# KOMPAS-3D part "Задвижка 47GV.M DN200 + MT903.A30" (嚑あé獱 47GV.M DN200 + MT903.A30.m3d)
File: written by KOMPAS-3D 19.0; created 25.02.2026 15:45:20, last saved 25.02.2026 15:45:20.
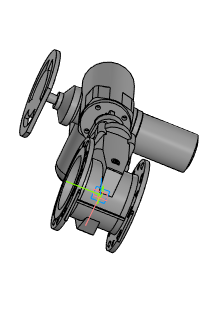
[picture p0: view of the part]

Document properties: Автор: Энергия; Полное имя файла: 47GV.M DN200\Задвижка 47GV.M DN200 с переходом под ISO фланец.a3d

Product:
- Part/product: Задвижка 47GV.M DN200 + MT903.A30
    Масса: 259.936
  - Component: Задвижка с обрезиненным клином DN200. Сборочный чертеж  | designation DR.47GVM.200.16.00.00СБ  | pos. 0  | Масса: 49.2062; Раздел спецификации: Документация; Форматы листов документа: 2xA3; source file: 47GV.M DN200\DR.47GVM.200.16.00.000 СБ - Задвижка с обрезиненным клином DN200.cdw
- Part/product: Задвижка 47GV.M DN200 + MT903.A30  | designation 01
    Масса: 49.1505
  - Component [detail]: Удлинитель шпинделя  | Материал: Сталь 20Х13 ГОСТ 5632-72 (density 7670 kg/m3); Масса: 1.06116; Раздел спецификации: Детали; Форматы листов документа: A3; source file: 47GV.M DN200\Удлинитель шпинделя DN200.m3d
  - Component [detail]: Стойка  | Материал: ВЧ50 ГОСТ 7293-85 (density 7200 kg/m3); Масса: 6.32319; Раздел спецификации: Детали; Форматы листов документа: 2xA3; source file: 47GV.M DN200\Стойка DN200.m3d
  - Component [standard]: Кольцо A50.50 ХГА ГОСТ 13943-86  | pos. 48  | Материал: Сталь 50 ХГА ГОСТ 14959-2016 (density 1000 kg/m3); Масса: 0.0068; Раздел спецификации: Стандартные изделия; Рассекать на разрезах: no
  - Component [assembly]: Клин с направляющими  | designation DR.47GVM.200.16.01.000  | pos. 2  | Раздел спецификации: Сборочные единицы; Форматы листов документа: A4; source file: 47GV.M DN200\DR.47GVM.200.16.01.000 - Клин с направляющими.a3d, 47GV.M DN200\DR.47GVM.200.16.01.000 - Клин с направляющими.spw, 47GV.M DN200\DR.47GVM.200.16.01.000 СБ - Клин с направляющими.cdw
  - Component [detail]: Шпиндель  | pos. 5  | Материал: Сталь 20Х13 ГОСТ 5632 - 2014 (density 7670 kg/m3); Масса: 0.28302; Раздел спецификации: Детали; Форматы листов документа: A3; source file: 47GV.M DN200\DR.47GVM.200.16.00.003 - Шпиндель.cdw, 47GV.M DN200\Шпиндель DN200.m3d
  - Component [detail]: Крышка DN200  | pos. 4  | Материал: ВЧ50 ГОСТ 7293-85 (density 7200 kg/m3); Масса: 27.3638; Раздел спецификации: Детали; Форматы листов документа: 2xA3; source file: 47GV.M DN200\DR.47GVM.200.16.00.002 - Крышка.cdw, 47GV.M DN200\Крышка DN200.m3d
  - Component [detail]: Корпус DN200  | pos. 3  | Материал: ВЧ50 ГОСТ 7293-85 (density 7200 kg/m3); Масса: 61.6368; Раздел спецификации: Детали; Форматы листов документа: 3xA3; source file: 47GV.M DN200\DR.47GVM.200.16.00.001 - Корпус.cdw, 47GV.M DN200\Корпус DN200.m3d
  - Component: Электропривод МТ903.А30 без блока управления  | Масса: 163.268; source file: 47GV.M DN200\Электропривод МТ903.А30 без блока управления.m3d

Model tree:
1. Операция без истории:1

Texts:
  Точка начала. Х
  Точка начала. Y
  Точка начала. Z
